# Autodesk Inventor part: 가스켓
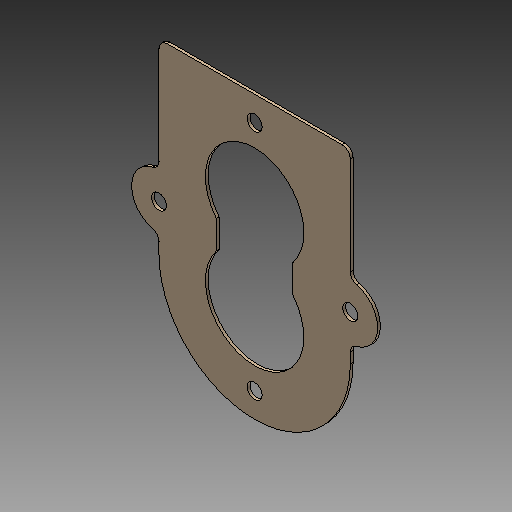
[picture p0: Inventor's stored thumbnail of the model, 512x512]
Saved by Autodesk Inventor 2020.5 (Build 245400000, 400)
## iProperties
Created: 2024-02
Part Number: 가스켓
Material: 스테인리스강
Document SubType Name: Modeling
Designer: mdu-01
Density: 1 g/cm^3
Appearance: 기본값(1)
Author: mdu-01
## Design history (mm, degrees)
sketch "스케치1"
  geometry: L1 (35, -4.851)-(35, 46) reference; L2 (35, 46)-(15, 46) reference; L3 (15, 37)-(15, 46) reference; L4 (12, 34)-(-12, 34) reference; L5 (-15, 37)-(-15, 46) reference; L6 (-35, 46)-(-15, 46) reference; L7 (-35, -4.851)-(-35, 46) reference; L8 (-35, -34)-(-35, -30.149) reference; L9 (35, -34)-(35, -30.149) reference; L10 (-14, -22.686)-(-14, -12.314) reference; L11 (14, -12.314)-(14, -22.686) reference; L12 (-35, -4.851)-(-35, 31); L13 (-32, 34)-(32, 34); L14 (35, 31)-(35, -4.851); C1 r 10 at (0, -1) reference; C2 r 10 at (0, -34) reference; C3 r 2.067 at (-35, -17.5) reference; C4 r 2.067 at (0, 25) reference; C5 r 2.067 at (0, -60) reference; C6 r 2.067 at (35, -17.5) reference; C7 r 2.75 at (0, 25); C8 r 2.75 at (35, -17.5); C9 r 2.75 at (-35, -17.5); C10 r 2.75 at (0, -60); A1 r 3 centre (12, 37) between (12, 34) and (15, 37) reference; A2 r 3 centre (-12, 37) between (-15, 37) and (-12, 34) reference; A3 r 3 centre (-38, -4.851) between (-37.308, -7.77) and (-35, -4.851) reference; A4 r 10 centre (-35, -17.5) between (-37.308, -7.77) and (-37.308, -27.23) reference; A5 r 3 centre (-38, -30.149) between (-35, -30.149) and (-37.308, -27.23) reference; A6 r 35 centre (0, -34) between (-35, -34) and (35, -34) reference; A7 r 3 centre (38, -30.149) between (37.308, -27.23) and (35, -30.149) reference; A8 r 10 centre (35, -17.5) between (37.308, -27.23) and (37.308, -7.77) reference; A9 r 3 centre (38, -4.851) between (35, -4.851) and (37.308, -7.77) reference; A10 r 18 centre (0, -1) between (14, -12.314) and (-14, -12.314) reference; A11 r 18 centre (0, -34) between (-14, -22.686) and (14, -22.686) reference; A12 r 3 centre (-32, 31) between (-32, 34) and (-35, 31); A13 r 3 centre (32, 31) between (35, 31) and (32, 34); 3 further points
  constraints: 6 centre point, 6 end point, 6 point on line, 6 tangent, 4 coincident, 4 equal radius, 4 point on circle, 2 collinear, 1 perpendicular
  dimensions: "d0" = 3 radius of A12; "d1" = 5.5 diameter of C7
extrude "돌출1" new body sketch "스케치1" distance "d2" = 1; taper "d3" = 0 deg
node "솔리드1"
node "참조1"
node "참조2"
node "참조3"
